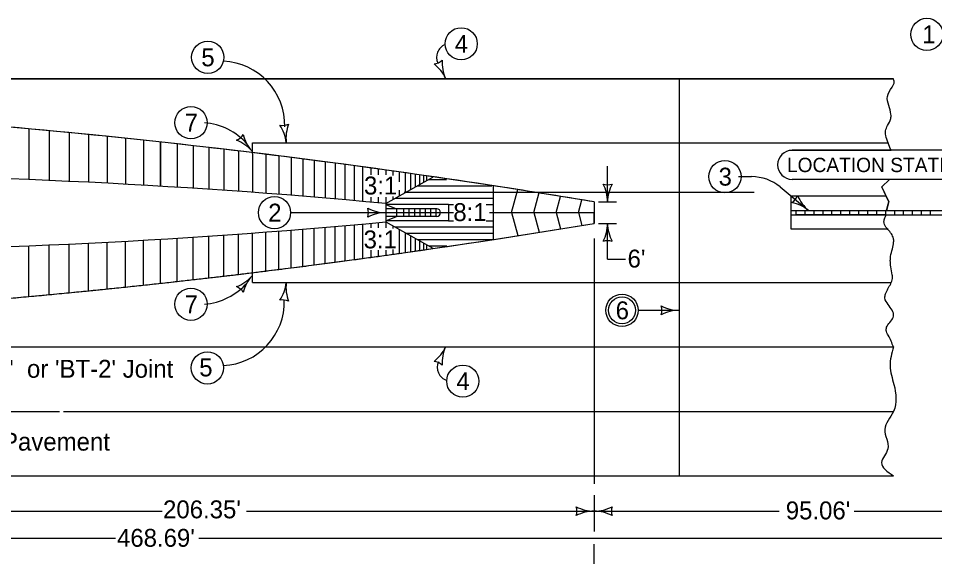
# Model space of a CAD drawing. Extents: x 10028 to 81668, y 3581 to 11018.
# Drawn here: x 11179 to 12202, y 8369 to 8979 of the extents above; entities that cross this region are included whole.
import ezdxf

# ---------------------------------------------------------------- set-up
doc = ezdxf.new("R2010")
doc.units = 0
for name, color, linetype in [('dsnCellsNorthArrow', 7, 'Continuous'), ('dsnStdLabel', 7, 'Continuous'), ('dsnStdShading', 7, 'Continuous'), ('dsnTextFinalPlan', 7, 'Continuous'), ('dsnTextTabulation', 7, 'Continuous'), ('Level 10', 7, 'Continuous'), ('Level 5', 7, 'Continuous'), ('Level 6', 7, 'Continuous'), ('SheetAddendum', 7, 'Continuous')]:
    doc.layers.add(name, color=color, linetype=linetype)

msp = doc.modelspace()

# ---------------------------------------------------------------- linework, layer by layer
at = {"layer": 'dsnCellsNorthArrow'}
for p, q in [((10316.5, 8539.5), (11224.8, 8539.5)), ((11228.9, 8539.5), (12155.5, 8539.5))]:
    msp.add_line(p, q, dxfattribs=at)
at = {"layer": 'dsnStdLabel'}
for p, q in [((12249.9, 8831.2), (12042.4, 8831.2)), ((12249.9, 8798.7), (12042.3, 8798.7))]:
    msp.add_line(p, q, dxfattribs=at)
msp.add_arc((12042.4, 8814.9), 16.2, 90, 270, dxfattribs=at)
at = {"layer": 'dsnStdShading'}
for p, q in [((11916.2, 8911.1), (10378.9, 8911.1)), ((12155.4, 8911.1), (11916.2, 8911.1)), ((11373.8, 8836.3), (11373.8, 8836.3)), ((12042.4, 8831.2), (12152.9, 8831.2)), ((12151.1, 8798.7), (12042.4, 8798.7)), ((12142.6, 8790.5), (12151.1, 8798.7)), ((11736.2, 8787.3), (11736.2, 8787.4)), ((12150.4, 8773.8), (12142.6, 8790.5)), ((11821.4, 8773.5), (11821.4, 8761.5)), ((11821.4, 8761.5), (11821.4, 8749.5)), ((12046.9, 8759.1), (12046.9, 8763.9)), ((11596.6, 8714.9), (11596.6, 8714.9)), ((11603.8, 8715.9), (11603.8, 8715.9)), ((11616.4, 8717.7), (11616.4, 8717.7)), ((11621.8, 8718.5), (11621.8, 8718.5)), ((11626.6, 8719.2), (11626.6, 8719.2)), ((11630.8, 8719.8), (11630.8, 8719.8)), ((11634.4, 8720.3), (11634.4, 8720.3)), ((11521, 8704.7), (11521, 8704.7)), ((11532.4, 8706.2), (11532.4, 8706.2)), ((11543.2, 8707.6), (11543.2, 8707.6)), ((11553.4, 8709), (11553.4, 8709)), ((11563, 8710.3), (11563, 8710.3)), ((11572, 8711.5), (11572, 8711.5)), ((11580.4, 8712.7), (11580.4, 8712.7)), ((11588.8, 8713.8), (11588.8, 8713.8)), ((11440, 8694.4), (11440, 8694.4)), ((11455, 8696.3), (11455, 8696.3)), ((11469.4, 8698), (11469.4, 8698)), ((11483.2, 8699.8), (11483.2, 8699.8)), ((11496.4, 8701.5), (11496.4, 8701.5)), ((11509, 8703.1), (11509, 8703.1)), ((11356, 8684.6), (11356, 8684.6)), ((11374, 8686.7), (11374, 8686.7)), ((11391.4, 8688.7), (11391.4, 8688.7)), ((11408.2, 8690.6), (11408.2, 8690.6)), ((11424.4, 8692.5), (11424.4, 8692.5)), ((11257, 8674.2), (11257, 8674.2)), ((11278, 8676.3), (11278, 8676.3)), ((11298.4, 8678.4), (11298.4, 8678.4)), ((11318.2, 8680.5), (11318.2, 8680.5)), ((11337.4, 8682.6), (11337.4, 8682.6)), ((11190.4, 8667.8), (11190.4, 8667.8)), ((11213.2, 8669.9), (11213.2, 8669.9)), ((11235.4, 8672), (11235.4, 8672)), ((10378, 8611.5), (11916.2, 8611.5)), ((11916.2, 8611.5), (12155.5, 8611.5))]:
    msp.add_line(p, q, dxfattribs=at)
for points in [[(11373.8, 8836.3), (11373.8, 8836.3)], [(12152.9, 8831.2), (12152.9, 8831.2)], [(11736.2, 8787.4), (11736.2, 8787.3)], [(12046.9, 8763.9), (12056.9, 8763.9), (12066.9, 8763.9), (12076.9, 8763.9), (12086.9, 8763.9), (12096.9, 8763.9), (12106.9, 8763.9), (12116.9, 8763.9), (12126.9, 8763.9), (12136.9, 8763.9), (12146.9, 8763.9), (12147.7, 8763.9)], [(12147.4, 8759.1), (12146.9, 8759.1), (12136.9, 8759.1), (12126.9, 8759.1), (12116.9, 8759.1), (12106.9, 8759.1), (12096.9, 8759.1), (12086.9, 8759.1), (12076.9, 8759.1), (12066.9, 8759.1), (12056.9, 8759.1), (12046.9, 8759.1)], [(12147.7, 8763.9), (12147.7, 8763.9)], [(11596.6, 8714.9), (11596.6, 8714.9)], [(11603.8, 8715.9), (11603.8, 8715.9)], [(11616.4, 8717.7), (11616.4, 8717.7)], [(11621.8, 8718.5), (11621.8, 8718.5)], [(11626.6, 8719.2), (11626.6, 8719.2)], [(11630.8, 8719.8), (11630.8, 8719.8)], [(11634.4, 8720.3), (11634.4, 8720.3)], [(11521, 8704.7), (11521, 8704.7)], [(11532.4, 8706.2), (11532.4, 8706.2)], [(11543.2, 8707.6), (11543.2, 8707.6)], [(11553.4, 8709), (11553.4, 8709)], [(11563, 8710.3), (11563, 8710.3)], [(11572, 8711.5), (11572, 8711.5)], [(11580.4, 8712.7), (11580.4, 8712.7)], [(11588.8, 8713.8), (11588.8, 8713.8)], [(11440, 8694.4), (11440, 8694.4)], [(11455, 8696.3), (11455, 8696.3)], [(11469.4, 8698), (11469.4, 8698)], [(11483.2, 8699.8), (11483.2, 8699.8)], [(11496.4, 8701.5), (11496.4, 8701.5)], [(11509, 8703.1), (11509, 8703.1)], [(11356, 8684.6), (11356, 8684.6)], [(11374, 8686.7), (11374, 8686.7)], [(11391.4, 8688.7), (11391.4, 8688.7)], [(11408.2, 8690.6), (11408.2, 8690.6)], [(11424.4, 8692.5), (11424.4, 8692.5)], [(11257, 8674.2), (11257, 8674.2)], [(11278, 8676.3), (11278, 8676.3)], [(11298.4, 8678.4), (11298.4, 8678.4)], [(11318.2, 8680.5), (11318.2, 8680.5)], [(11337.4, 8682.6), (11337.4, 8682.6)], [(11190.4, 8667.8), (11190.4, 8667.8)], [(11213.2, 8669.9), (11213.2, 8669.9)], [(11235.4, 8672), (11235.4, 8672)]]:
    msp.add_lwpolyline(points, dxfattribs=at)
for centre, radius, start, end in [((10403, 294.3), 8597, 83.51664, 86.48991), ((10403, 294.3), 8597, 81.07917, 83.51663), ((12042.4, 8814.9), 16.2, 90, 270), ((10403, 294.3), 8597, 80.50385, 81.07911), ((10403.1, 17227.3), 8595.6, 278.23561, 279.49716), ((10403.1, 17227.3), 8595.6, 277.9286, 277.9811), ((10403.1, 17227.3), 8595.6, 277.9811, 278.02957), ((10403.1, 17227.3), 8595.6, 278.02957, 278.11439), ((10403.1, 17227.3), 8595.6, 278.11439, 278.15075), ((10403.1, 17227.3), 8595.6, 278.15075, 278.18308), ((10403.1, 17227.3), 8595.6, 278.18308, 278.21136), ((10403.1, 17227.3), 8595.6, 278.21136, 278.23561), ((10403.1, 17227.3), 8595.6, 277.39189, 277.47256), ((10403.1, 17227.3), 8595.6, 277.47256, 277.5492), ((10403.1, 17227.3), 8595.6, 277.5492, 277.62183), ((10403.1, 17227.3), 8595.6, 277.62183, 277.69043), ((10403.1, 17227.3), 8595.6, 277.69043, 277.755), ((10403.1, 17227.3), 8595.6, 277.75501, 277.81555), ((10403.1, 17227.3), 8595.6, 277.81555, 277.87207), ((10403.1, 17227.3), 8595.6, 277.87208, 277.9286), ((10403.1, 17227.3), 8595.6, 276.8236, 276.92834), ((10403.1, 17227.3), 8595.6, 276.92834, 277.02907), ((10403.1, 17227.3), 8595.6, 277.02907, 277.1258), ((10403.1, 17227.3), 8595.6, 277.1258, 277.21851), ((10403.1, 17227.3), 8595.6, 277.21851, 277.30721), ((10403.1, 17227.3), 8595.6, 277.30721, 277.39189), ((10403.1, 17227.3), 8595.6, 276.2399, 276.36463), ((10403.1, 17227.3), 8595.6, 276.36463, 276.48537), ((10403.1, 17227.3), 8595.6, 276.48537, 276.60212), ((10403.1, 17227.3), 8595.6, 276.60212, 276.71486), ((10403.1, 17227.3), 8595.6, 276.71486, 276.8236), ((10403.1, 17227.3), 8595.6, 275.55638, 275.70105), ((10403.1, 17227.3), 8595.6, 275.70105, 275.84175), ((10403.1, 17227.3), 8595.6, 275.84175, 275.97845), ((10403.1, 17227.3), 8595.6, 275.97845, 276.11117), ((10403.1, 17227.3), 8595.6, 276.11117, 276.2399), ((10403.1, 17227.3), 8595.6, 275.09846, 275.25508), ((10403.1, 17227.3), 8595.6, 275.25508, 275.40772), ((10403.1, 17227.3), 8595.6, 275.40772, 275.55638)]:
    msp.add_arc(centre, radius, start, end, dxfattribs=at)
for points in [[(12152.9, 8831.2), (12147, 8847.8), (12146.7, 8853), (12149, 8858.8), (12152.5, 8866.5), (12152.7, 8871.4), (12150.2, 8881.2), (12148.7, 8891.3), (12154, 8901.7), (12156.3, 8907.7), (12155.4, 8911.1)], [(12155.5, 8611.5), (12149.7, 8624.5), (12147.4, 8630), (12148.4, 8634.7), (12152.6, 8640.3), (12155.7, 8645.9), (12154, 8652.4), (12149.6, 8658.9), (12145.9, 8666.2), (12146.8, 8670.9), (12152.4, 8682), (12154.5, 8687.8), (12154.1, 8692.1), (12152.6, 8701.1), (12152, 8708.1), (12152.3, 8712.4), (12154.3, 8721.2), (12155.7, 8728.4), (12155.5, 8732.8), (12153.2, 8737.8), (12149.3, 8742.7), (12145.5, 8748.3), (12144.9, 8751.5), (12145.8, 8755.6), (12147.4, 8759.1)]]:
    msp.add_spline(points, degree=3, dxfattribs=at)
msp.add_open_spline([(12147.7, 8763.9), (12148.6, 8767.2), (12149.5, 8770.5), (12150.4, 8773.8)], degree=2, dxfattribs=at)
at = {"layer": 'dsnTextFinalPlan'}
for p, q in [((11836.4, 8773.5), (11836.4, 8813.5)), ((11982.4, 8801.7), (11997.1, 8801.7)), ((12028.9, 8790.2), (12060.8, 8763.9)), ((11482.6, 8761.5), (11588.7, 8761.5)), ((11836.4, 8709.5), (11836.4, 8749.5)), ((11821.4, 8732.6), (11821.4, 8458.6)), ((11836.4, 8709.5), (11856.4, 8709.5)), ((11870.5, 8652.4), (11916.2, 8652.4)), ((11821.4, 8446.1), (11821.4, 8405.5)), ((10924.3, 8428.1), (11339.4, 8428.1)), ((11433.4, 8428.1), (11821.4, 8428.1)), ((11821.4, 8428.1), (12028, 8428.1)), ((12111.8, 8428.1), (12332.9, 8428.1)), ((10378, 8398.1), (11287.3, 8398.1)), ((11380, 8398.1), (12332.9, 8398.1)), ((11821.4, 8369.4), (11821.4, 8391.2))]:
    msp.add_line(p, q, dxfattribs=at)
for centre, radius, start, end in [((11660.5, 8935.1), 15, 111.3824, 205.2927), ((11404.6, 8859.1), 71.5, 358.5257, 87.654), ((11640.7, 8943.9), 16.4, 276.8646, 312.3313), ((11694.2, 8929.2), 42.5, 176.5254, 204.5979), ((11616.9, 8893.8), 42.5, 24.5979, 52.6704), ((11381.4, 8792), 70, 40.9906, 85.9043), ((11473.7, 8875.4), 16.4, 258.6446, 294.1113), ((11435.5, 8835.2), 42.5, 6.3779, 34.4504), ((11519.9, 8844.7), 42.5, 158.3054, 186.3779), ((11415.8, 8857.4), 16.4, 293.2594, 328.7261), ((11471.2, 8858.4), 42.5, 192.9203, 220.9928), ((11407.1, 8802.6), 42.5, 40.9928, 69.0653), ((11997.1, 8751.7), 50, 50.4322, 90), ((11836.4, 8809.1), 16.4, 252.2666, 287.7333), ((11793.9, 8773.5), 42.5, 0, 28.0725), ((11878.9, 8773.5), 42.5, 151.9275, 180), ((12033.3, 8786.6), 16.4, 302.6988, 338.1655), ((12087.9, 8796.6), 42.5, 202.3597, 230.4322), ((11553.1, 8761.5), 16.4, 342.2666, 17.7333), ((11588.7, 8804), 42.5, 241.9275, 270), ((12033.7, 8731.1), 42.5, 50.4322, 78.5047), ((11588.7, 8719), 42.5, 90, 118.0725), ((11793.9, 8749.5), 42.5, 331.9275, 0), ((11878.9, 8749.5), 42.5, 180, 208.0725), ((11836.4, 8713.8), 16.4, 72.2666, 107.7334), ((11407.1, 8718.6), 42.5, 290.9347, 319.0072), ((11471.2, 8662.8), 42.5, 139.0072, 167.0797), ((11381.4, 8729.2), 70, 274.0957, 319.0094), ((11415.8, 8663.8), 16.4, 31.2739, 66.7406), ((11435.5, 8687.7), 42.5, 325.5496, 353.6221), ((11519.9, 8678.3), 42.5, 173.6221, 201.6946), ((11404.1, 8662.1), 71.5, 272.6651, 1.4743), ((11473.7, 8647.6), 16.4, 65.8887, 101.3554), ((11880.6, 8652.4), 16.4, 342.2666, 17.7333), ((11916.2, 8694.9), 42.5, 241.9275, 270), ((11916.2, 8609.9), 42.5, 90, 118.0725), ((11616.9, 8629.2), 42.5, 307.3296, 335.4021), ((11694.2, 8593.8), 42.5, 155.4021, 183.4746), ((11640.7, 8579.1), 16.4, 47.6687, 83.1354), ((11661.3, 8588.6), 15, 154.7073, 252.9017), ((11785.7, 8428.1), 16.4, 342.2666, 17.7333), ((11821.4, 8470.6), 42.5, 241.9275, 270), ((11821.4, 8470.6), 42.5, 270, 298.0725), ((11857, 8428.1), 16.4, 162.2666, 197.7334), ((11821.4, 8385.6), 42.5, 90, 118.0725), ((11821.4, 8385.6), 42.5, 61.9275, 90)]:
    msp.add_arc(centre, radius, start, end, dxfattribs=at)
at = {"layer": 'dsnTextTabulation'}
msp.add_line((11609.2, 8784.4), (12000.1, 8784.4), dxfattribs=at)
msp.add_circle((11852.5, 8652.4), 15, dxfattribs=at)
at = {"layer": 'Level 10'}
for centre in [(12192.8, 8960.6), (11673, 8950.1), (11390.1, 8935), (11371.4, 8862), (11967.4, 8801.7), (11464.6, 8761.5), (11371.4, 8659.2), (11852.5, 8652.4), (11389.7, 8588.1), (11674.8, 8573.3)]:
    msp.add_circle(centre, 18, dxfattribs=at)
at = {"layer": 'Level 5'}
msp.add_arc((11645.7, 8761.5), 4.2, 270, 90, dxfattribs=at)
at = {"layer": 'SheetAddendum'}
for p, q in [((10378.9, 8911.1), (11916.2, 8911.1)), ((11916.2, 8911.1), (11916.2, 8839.5)), ((11916.2, 8911.1), (12155.4, 8911.1)), ((11190.4, 8855.1), (11190.4, 8798.4)), ((11213.2, 8853), (11213.2, 8797.4)), ((11235.4, 8850.9), (11235.4, 8796.4)), ((11257, 8848.8), (11257, 8795.4)), ((11278, 8846.6), (11278, 8794.3)), ((11298.4, 8844.5), (11298.4, 8793.2)), ((11318.2, 8842.4), (11318.2, 8792.1)), ((11337.4, 8840.3), (11337.4, 8791)), ((11337.4, 8791), (11337.4, 8840.3)), ((11356, 8838.3), (11356, 8789.8)), ((11440, 8827.5), (11440, 8839.5)), ((11440, 8839.5), (12150, 8839.5)), ((11916.2, 8839.5), (11916.2, 8611.5)), ((11373.8, 8836.3), (11373.8, 8788.7)), ((11391.4, 8834.3), (11391.4, 8787.5)), ((11408.2, 8832.3), (11408.2, 8786.4)), ((11424.4, 8830.4), (11424.4, 8785.2)), ((11440, 8827.5), (11440, 8784.1)), ((11455, 8826.7), (11455, 8783)), ((11469.4, 8824.9), (11469.4, 8781.9)), ((11483.2, 8823.1), (11483.2, 8780.8)), ((11496.4, 8821.5), (11496.4, 8779.8)), ((11509, 8819.8), (11509, 8778.7)), ((11521, 8818.3), (11521, 8777.7)), ((11532.4, 8816.8), (11532.4, 8776.8)), ((11543.2, 8815.3), (11543.2, 8775.8)), ((11553.4, 8814), (11553.4, 8774.9)), ((11563, 8812.7), (11563, 8774.1)), ((11572, 8811.4), (11572, 8803.7)), ((11580.4, 8810.3), (11580.4, 8803.7)), ((11588.8, 8809.1), (11588.8, 8803.7)), ((11596.6, 8808), (11596.6, 8802.9)), ((11603.8, 8807), (11603.8, 8795.9)), ((11588.8, 8771.7), (11641.4, 8801.1)), ((11610.4, 8806.1), (11610.4, 8783.8)), ((11616.4, 8805.2), (11616.4, 8787.1)), ((11621.8, 8804.4), (11621.8, 8790.1)), ((11626.6, 8803.8), (11626.6, 8792.8)), ((11630.8, 8803.2), (11630.8, 8795.2)), ((11634.4, 8802.6), (11634.4, 8797.2)), ((11636.7, 8798.4), (11656.5, 8798.4)), ((12142.6, 8790.5), (12151.1, 8798.7)), ((11603.8, 8786.6), (11603.8, 8780.1)), ((11624.1, 8791.4), (11707.3, 8791.4)), ((11708.7, 8791.2), (11708.7, 8731.7)), ((11729.3, 8761.5), (11736.2, 8787.4)), ((12150.4, 8773.7), (12142.6, 8790.5)), ((11572, 8778.7), (11572, 8773.3)), ((11580.4, 8778.7), (11580.4, 8772.5)), ((11580.4, 8778), (11580.4, 8776.8)), ((11588.8, 8778.7), (11588.8, 8744.7)), ((11596.6, 8779.5), (11596.6, 8776)), ((11599.2, 8777.5), (11708.7, 8777.5)), ((11611.6, 8784.5), (11708.7, 8784.5)), ((11754.1, 8761.5), (11760.1, 8783.9)), ((11779, 8761.5), (11783.8, 8779.6)), ((12041, 8780.3), (12041, 8743.5)), ((12041, 8780.3), (12147.5, 8780.3)), ((11588.7, 8771.7), (11588.7, 8751.2)), ((11658.9, 8770.5), (11588.7, 8770.5)), ((11588.7, 8770.5), (11600.7, 8765.7)), ((11658.9, 8770.5), (11658.9, 8752.5)), ((11658.9, 8770.5), (11664.5, 8770.5)), ((11700.7, 8770.5), (11708.7, 8770.5)), ((11803.8, 8761.5), (11807.6, 8775.7)), ((11821.4, 8773.5), (11821.4, 8761.5)), ((11821.4, 8773.5), (11821.4, 8749.5)), ((11826.4, 8773.5), (11846.4, 8773.5)), ((12150.4, 8773.8), (12147.7, 8763.9)), ((11600.7, 8765.7), (11588.7, 8765.7)), ((11588.7, 8761.5), (11664.5, 8761.5)), ((11588.7, 8752.5), (11600.7, 8757.3)), ((11600.7, 8757.3), (11588.7, 8757.3)), ((11645.7, 8765.7), (11600.7, 8765.7)), ((11600.7, 8765.7), (11600.7, 8757.3)), ((11645.7, 8757.3), (11600.7, 8757.3)), ((11608.7, 8765.7), (11608.7, 8757.3)), ((11614.7, 8765.7), (11614.7, 8757.3)), ((11620.7, 8765.7), (11620.7, 8757.3)), ((11626.7, 8765.7), (11626.7, 8757.3)), ((11632.7, 8765.7), (11632.7, 8757.3)), ((11638.7, 8765.7), (11638.7, 8757.3)), ((11644.7, 8765.7), (11644.7, 8757.3)), ((11704.6, 8761.5), (11821.4, 8761.5)), ((11729.3, 8761.5), (11736.1, 8735.9)), ((11754.1, 8761.5), (11760, 8739.6)), ((11779, 8761.5), (11783.8, 8743.4)), ((11803.8, 8761.5), (11807.6, 8747.2)), ((11821.4, 8749.5), (11821.4, 8761.5)), ((12041.2, 8763.9), (12369.2, 8763.9)), ((12041.2, 8759.1), (12367.4, 8759.1)), ((12046.9, 8759.1), (12046.9, 8763.9)), ((12056.9, 8759.1), (12056.9, 8763.9)), ((12066.9, 8759.1), (12066.9, 8763.9)), ((12076.9, 8759.1), (12076.9, 8763.9)), ((12086.9, 8759.1), (12086.9, 8763.9)), ((12096.9, 8759.1), (12096.9, 8763.9)), ((12106.9, 8759.1), (12106.9, 8763.9)), ((12116.9, 8759.1), (12116.9, 8763.9)), ((12126.9, 8759.1), (12126.9, 8763.9)), ((12136.9, 8759.1), (12136.9, 8763.9)), ((12146.9, 8759.1), (12146.9, 8763.9)), ((12156.9, 8759.1), (12156.9, 8763.9)), ((12166.9, 8759.1), (12166.9, 8763.9)), ((12176.9, 8759.1), (12176.9, 8763.9)), ((12186.9, 8759.1), (12186.9, 8763.9)), ((12196.9, 8759.1), (12196.9, 8763.9)), ((11532.4, 8706.2), (11532.4, 8746.2)), ((11543.2, 8747.1), (11543.2, 8707.6)), ((11553.4, 8748), (11553.4, 8709)), ((11563, 8748.9), (11563, 8710.3)), ((11572, 8749.7), (11572, 8744.7)), ((11580.4, 8750.4), (11580.4, 8744.7)), ((11658.9, 8752.5), (11588.7, 8752.5)), ((11588.8, 8751.2), (11641.5, 8721.8)), ((11596.6, 8746.9), (11596.6, 8743.8)), ((11599.1, 8745.5), (11708.7, 8745.5)), ((11658.9, 8752.5), (11664.5, 8752.5)), ((11700.8, 8752.5), (11708.7, 8752.5)), ((11826.4, 8749.5), (11846.4, 8749.5)), ((11391.4, 8688.7), (11391.4, 8735.4)), ((11408.2, 8690.6), (11408.2, 8736.5)), ((11424.4, 8692.5), (11424.4, 8737.7)), ((11440, 8694.4), (11440, 8738.8)), ((11455, 8696.3), (11455, 8739.9)), ((11469.4, 8698), (11469.4, 8741)), ((11483.2, 8699.8), (11483.2, 8742.1)), ((11496.4, 8701.5), (11496.4, 8743.2)), ((11509, 8703.1), (11509, 8744.2)), ((11521, 8704.7), (11521, 8745.2)), ((11603.8, 8742.9), (11603.8, 8715.9)), ((11610.4, 8739.2), (11610.4, 8717.4)), ((11611.6, 8738.5), (11708.7, 8738.5)), ((11616.4, 8735.9), (11616.4, 8717.7)), ((12041, 8743.5), (12149.5, 8743.5)), ((11213.2, 8669.9), (11213.2, 8725.5)), ((11235.4, 8672), (11235.4, 8726.5)), ((11257, 8674.2), (11257, 8727.6)), ((11278, 8676.3), (11278, 8728.6)), ((11298.4, 8678.4), (11298.4, 8729.7)), ((11318.2, 8680.5), (11318.2, 8730.8)), ((11337.4, 8682.6), (11337.4, 8732)), ((11356, 8684.6), (11356, 8733.1)), ((11374, 8686.7), (11374, 8734.3)), ((11621.8, 8732.8), (11621.8, 8718.5)), ((11624.1, 8731.6), (11707.8, 8731.6)), ((11626.6, 8730.2), (11626.6, 8719.2)), ((11630.8, 8727.8), (11630.8, 8719.8)), ((11634.4, 8725.8), (11634.4, 8720.3)), ((11190.4, 8667.8), (11190.4, 8724.6)), ((11572, 8719.7), (11572, 8711.5)), ((11580.4, 8719.7), (11580.4, 8712.7)), ((11588.8, 8719.7), (11588.8, 8713.8)), ((11596.6, 8720.5), (11596.6, 8714.9)), ((11636.7, 8724.6), (11657, 8724.6)), ((11440, 8683.5), (11440, 8695.5)), ((11440, 8683.5), (12153, 8683.5)), ((10378, 8611.5), (11916.2, 8611.5)), ((11916.2, 8611.5), (11916.2, 8467.5)), ((11916.2, 8611.5), (12155.5, 8611.5)), ((10316.5, 8467.5), (12155.5, 8467.5))]:
    msp.add_line(p, q, dxfattribs=at)
for centre, radius, start, end in [((10403, 294.3), 8597, 80.50385, 86.52493), ((10880.2, 1171.4), 7633.3, 84.67428, 90), ((10880.2, 16351.5), 7633.3, 270, 275.32661), ((10403.1, 17227.3), 8595.6, 273.47608, 279.49716)]:
    msp.add_arc(centre, radius, start, end, dxfattribs=at)
for points in [[(12152.9, 8831.2), (12147, 8847.8), (12146.7, 8853), (12149, 8858.8), (12152.5, 8866.5), (12152.7, 8871.4), (12150.2, 8881.2), (12148.7, 8891.3), (12154, 8901.7), (12156.3, 8907.7), (12155.4, 8911.1)], [(12155.5, 8611.5), (12149.7, 8624.5), (12147.4, 8630), (12148.4, 8634.7), (12152.6, 8640.3), (12155.7, 8645.9), (12154, 8652.4), (12149.6, 8658.9), (12145.9, 8666.2), (12146.8, 8670.9), (12152.4, 8682), (12154.5, 8687.8), (12154.1, 8692.1), (12152.6, 8701.1), (12152, 8708.1), (12152.3, 8712.4), (12154.3, 8721.2), (12155.7, 8728.4), (12155.5, 8732.8), (12153.2, 8737.8), (12149.3, 8742.7), (12145.5, 8748.3), (12144.9, 8751.5), (12145.8, 8755.6), (12147.4, 8759.1)], [(12155.5, 8611.5), (12151.7, 8590.3), (12156, 8569.7), (12155.5, 8539.5), (12145.7, 8519.2), (12149.2, 8497.8), (12142.3, 8482.4), (12155.5, 8467.5)]]:
    msp.add_spline(points, degree=3, dxfattribs=at)

# ---------------------------------------------------------------- texts
at = {"layer": 'dsnStdLabel'}
msp.add_text('LOCATION STATION', height=16, dxfattribs=at).set_placement((12036.6, 8806.8))
at = {"layer": 'Level 6'}
for s, p in [('1', (12187.6, 8950.6)), ('4', (11665.9, 8940.1)), ('5', (11382.9, 8925)), ('7', (11364.3, 8852)), ('3', (11960.3, 8791.7)), ('3:1', (11564.5, 8781.8)), ('2', (11457.6, 8751.5)), ('8:1', (11664.2, 8752.1)), ('3:1', (11564.1, 8721.6)), ("6'", (11858.7, 8700.2)), ('7', (11364.3, 8649.2)), ('6', (11845.4, 8642.4)), ("'L-2'  or 'BT-2' Joint", (11124.6, 8577.1)), ('5', (11380.6, 8578.6)), ('4', (11667.7, 8563.3)), ('Existing Pavement', (11059.4, 8495.7)), ("206.35'", (11340.2, 8420.1)), ("95.06'", (12035.3, 8418.9)), ("468.69'", (11288.8, 8388.3))]:
    msp.add_text(s, height=20, dxfattribs=at).set_placement(p)

doc.saveas('drawing.dxf')
